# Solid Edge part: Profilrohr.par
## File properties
Username: ahadarics
Dokumentum tartalom típus: 0
Author: ahadarics
Last saved by: ahadarics
Revision: 78
Sűrűség: 0,000 kg/m^3
Pontosság: 0,990
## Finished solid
Body 1: solid body, 6 faces, 6 edges, 0 vertices.
  Faces by surface: cone 2, cylinder 2, plane 2
  Edges by curve: circle 6
Bounding box of the edges (mm): 11.270 x 11.270 x 75.500, from (-5.635, -5.635, -57.75) to (5.635, 5.635, 17.75).
Cylindrical faces by radius (mm): R5 x1, R5.635 x1
Conical faces (half-angle, radius in mm at the cone's reference point): 15 deg R5.067 x2
Planar faces by outward normal: +z 1, -z 1
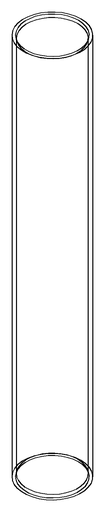
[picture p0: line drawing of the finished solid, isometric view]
